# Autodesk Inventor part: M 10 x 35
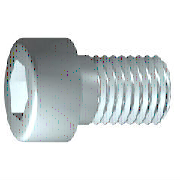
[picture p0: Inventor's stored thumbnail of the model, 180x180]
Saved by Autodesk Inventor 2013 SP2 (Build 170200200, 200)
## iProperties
IsCustomPart: 0
Created: 2009-02
Part Number: M 10 x 35
Material: 강, 연강
Description: 6각머리 태핑 나사
Document SubType Name: Modeling
Standard: KS B 1003
Designer: KYOUNG IL JANG
Standards Organization: KS
Language: ko-KR
Size Designation: M 10 x 35
Categories: <MemberInstance><Categories><Category DisplayName="조임쇠" InternalName="e4da775c-781d-43d5-af7c-5136215cf5a6" Mnemonic="FSTN"><Category DisplayName="볼트" InternalN
Density: 1 g/cm^3
Author: KYOUNG IL JANG
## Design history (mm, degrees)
sketch "스케치1"
  geometry: L1 (-2.333, 0)-(35, 0); L2 (35, 0)-(35, 5); L3 (35, 5)-(3.75, 5); L4 (3.75, 5)-(2.83, 5); L5 (2.83, 5)-(0, 5); L6 (0, 5)-(0, 8); L7 (0, 8)-(-10, 8); L8 (-10, 8)-(-10, 4.619); L9 (-10, 4.619)-(-5, 4.619); L10 (-5, 4.619)-(-2.333, 0); L11 (-19, 0)-(44, 0) reference; L12 (0, -1.6)-(0, 9.6) reference; L13 (3.75, 5)-(0, 5)
  constraints: 22 end point, 6 parallel, 2 collinear, 2 perpendicular, 1 horizontal, 1 point on line
  dimensions: "d1" = 31.25 distance from line of L3.end L2 (= GEL); "d2" = 0.92028 distance of L4.end L3.end (computed from GAL); "d3" = 10 distance between parallel lines of L8 L6 (= KOH); "d4" = 5 distance of L8.end L9.end (= INTI); "d5" = 60 deg angle of L10 L1; "d6" = 10 diameter of L3 L1 (= GD); "d7" = 10 diameter of L5 L1 (= BDM); "d8" = 9.2376 diameter of L9 L1 (= 1.1547 x SW); "d9" = 16 diameter of L7 L1 (= KOD); "d26" = 35 distance between parallel lines of L12 L2 (= NLG)
revolve "본체" sketch "스케치1" stored, may be unused: angle "d10" = 90 deg
sketch "스케치2"
  geometry: L1 (0, -11.2)-(0, 11.2) reference; L2 (-11.2, 0)-(11.2, 0) reference; L3 (4.619, 0)-(2.309, -4); L4 (2.309, -4)-(-2.309, -4); L5 (-2.309, -4)-(-4.619, 0); L6 (-4.619, 0)-(-2.309, 4); L7 (-2.309, 4)-(2.309, 4); L8 (2.309, 4)-(4.619, 0); 2 further points
  constraints: 12 end point, 1 coincident, 1 horizontal alignment, 1 point on line, 12 other
extrude "슬롯" join sketch "스케치2" stored distance "d11" = 10; taper "d12" = 0 deg
workplane "Work Plane1"
fillet "Fillet2" dims "d30" = 0.1 (= R)
body "Solid1"
fillet "모깎기1" dims "d17" = 1 (= RR)
feature "스레드" dims "d13" = 31.25 (= GEL), "d14" = 0
chamfer "모따기1" distance "d15" = 0.92018 (= -0.5 x SPD + 0.5 x GD); stored, may be unused: second distance "d16" = 0.92018 (= GUL), angle "d27" = 45 deg
other parameters: "GD" = 10 (= NND) [user parameter; used in 2 equation terms], "NLG" = 35 [user parameter; used in 1 equation term], "GEL" = 31.25 [user parameter; used in 2 equation terms], "KOD" = 16 [user parameter; used in 1 equation term], "KOH" = 10 [user parameter; used in 1 equation term], "INTI" = 5 [user parameter; used in 1 equation term], "GAL" = 0.92018 (= 0.61345 x PTC) [user parameter; used in 1 equation term], "GUL" = 0.92018 (= 0.61345 x PTC) [user parameter; used in 1 equation term], "BDM" = 10 (= NND) [user parameter; used in 1 equation term], "SW" = 8 [user parameter; used in 2 equation terms], "RR" = 1 [user parameter; used in 1 equation term], "SPD" = 8.15965 (= NND - 1.2269 x PTC) [user parameter; used in 1 equation term], "d19" = 0, "d28" = 0, "d29" = 0, "R" = 0.1 [user parameter; used in 1 equation term], "PHH" = 0.4 [user parameter], "GD1" = 8.15965 (= THREADDIA - 1.2269 x PTC) [user parameter], "FAWI" = 45 deg [user parameter], "TPU" = 6.66667 (computed from PTC) [user parameter], "PTC" = 1.5 [user parameter; used in 5 equation terms], "TOA" = 30 deg [user parameter], "E0" = 9.24 (= 1.155 x SW) [user parameter]
